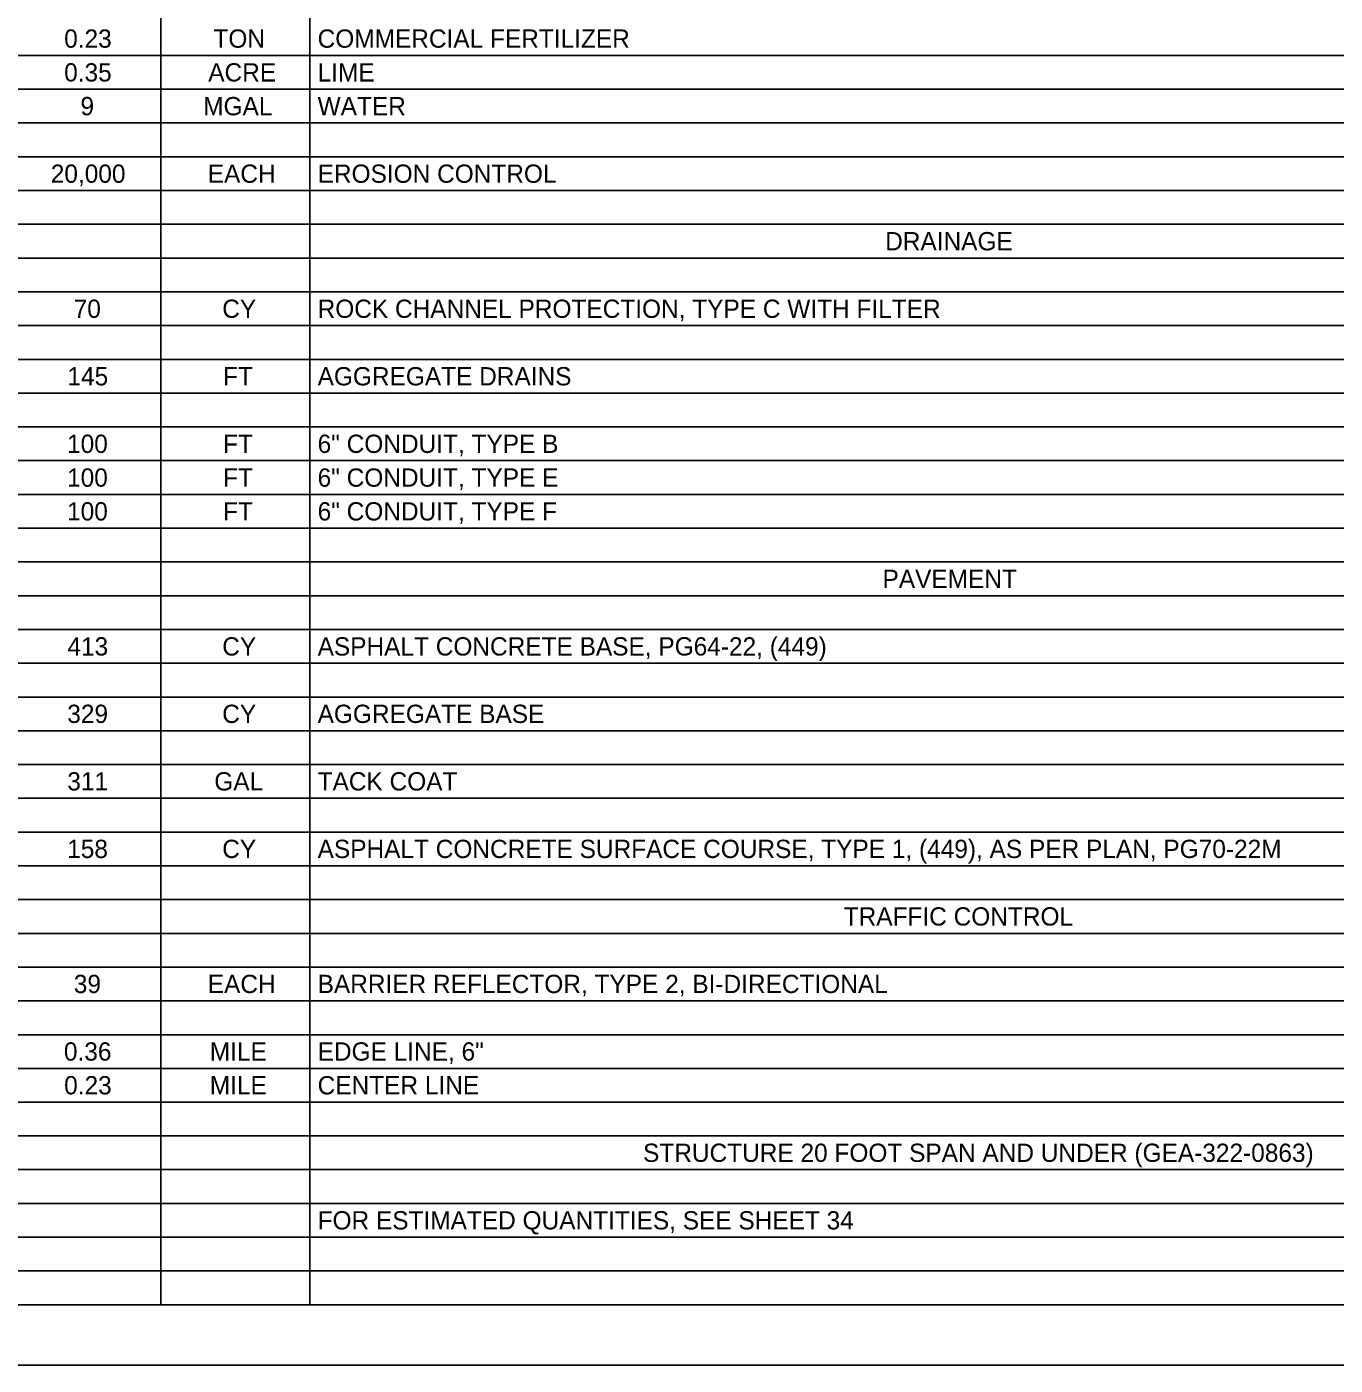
# Model space of a CAD drawing. Extents: x -31.7 to 37.3, y 0 to 22.
# Drawn here: x 18.16 to 29.01, y 0 to 11.1 of the extents above; entities that cross this region are included whole.
import ezdxf

# ---------------------------------------------------------------- set-up
doc = ezdxf.new("R2010")
doc.units = 0
for name, color, linetype in [('SH_Border', 7, 'Continuous'), ('SH_Cut_Line', 7, 'Continuous'), ('SH_Data', 7, 'Continuous'), ('SH_Text', 7, 'Continuous')]:
    doc.layers.add(name, color=color, linetype=linetype)

msp = doc.modelspace()

# ---------------------------------------------------------------- linework, layer by layer
at = {"layer": 'SH_Border'}
msp.add_lwpolyline([(1.5, 21.5), (33.5, 21.5), (33.5, 0.5), (1.5, 0.5)], close=True, dxfattribs=at)
at = {"layer": 'SH_Cut_Line'}
msp.add_lwpolyline([(0, 0), (34, 0), (34, 22), (0, 22)], close=True, dxfattribs=at)
at = {"layer": 'SH_Data'}
for p, q in [((19.27, 21.5), (19.27, 0.502)), ((20.506, 21.5), (20.506, 0.502)), ((1.5, 10.861), (32.001, 10.861)), ((1.5, 10.581), (32.001, 10.581)), ((1.5, 10.301), (32.001, 10.301)), ((1.5, 10.021), (32.001, 10.021)), ((1.5, 9.741), (32.001, 9.741)), ((1.5, 9.461), (32.001, 9.461)), ((1.5, 9.181), (32.001, 9.181)), ((1.5, 8.901), (32.001, 8.901)), ((1.5, 8.621), (32.001, 8.621)), ((1.5, 8.341), (32.001, 8.341)), ((1.5, 8.061), (32.001, 8.061)), ((1.5, 7.781), (32.001, 7.781)), ((1.5, 7.501), (32.001, 7.501)), ((1.5, 7.221), (32.001, 7.221)), ((1.5, 6.941), (32.001, 6.941)), ((1.5, 6.661), (32.001, 6.661)), ((1.5, 6.381), (32.001, 6.381)), ((1.5, 6.101), (32.001, 6.101)), ((1.5, 5.821), (32.001, 5.821)), ((1.5, 5.541), (32.001, 5.541)), ((1.5, 5.261), (32.001, 5.261)), ((1.5, 4.981), (32.001, 4.981)), ((1.5, 4.701), (32.001, 4.701)), ((1.5, 4.421), (32.001, 4.421)), ((1.5, 4.141), (32.001, 4.141)), ((1.5, 3.861), (32.001, 3.861)), ((1.5, 3.581), (32.001, 3.581)), ((1.5, 3.301), (32.001, 3.301)), ((1.5, 3.021), (32.001, 3.021)), ((1.5, 2.741), (32.001, 2.741)), ((1.5, 2.461), (32.001, 2.461)), ((1.5, 2.182), (32.001, 2.182)), ((1.5, 1.902), (32.001, 1.902)), ((1.5, 1.622), (32.001, 1.622)), ((1.5, 1.342), (32.001, 1.342)), ((1.5, 1.062), (32.001, 1.062)), ((1.5, 0.782), (32.001, 0.782)), ((1.5, 0.502), (32.001, 0.502))]:
    msp.add_line(p, q, dxfattribs=at)

# ---------------------------------------------------------------- texts
at = {"layer": 'SH_Text'}
for s, height, p in [('0.23', 0.1515, (18.469, 10.925)), ('TON', 0.1515, (19.707, 10.925)), ('COMMERCIAL FERTILIZER', 0.15152, (20.571, 10.925)), ('0.35', 0.1515, (18.469, 10.645)), ('ACRE', 0.1515, (19.664, 10.645)), ('LIME', 0.1515, (20.571, 10.645)), ('9', 0.152, (18.604, 10.365)), ('MGAL', 0.1515, (19.622, 10.365)), ('WATER', 0.1515, (20.571, 10.365)), ('20,000', 0.1515, (18.358, 9.805)), ('EACH', 0.1515, (19.66, 9.805)), ('EROSION CONTROL', 0.15152, (20.571, 9.805)), ('DRAINAGE', 0.1515, (25.278, 9.245)), ('70', 0.1515, (18.548, 8.685)), ('CY', 0.1515, (19.78, 8.685)), ('ROCK CHANNEL PROTECTION, TYPE C WITH FILTER', 0.15152, (20.571, 8.685)), ('145', 0.1515, (18.496, 8.125)), ('FT', 0.1515, (19.787, 8.125)), ('AGGREGATE DRAINS', 0.15152, (20.571, 8.125)), ('100', 0.1515, (18.493, 7.565)), ('FT', 0.1515, (19.787, 7.565)), ('6" CONDUIT, TYPE B', 0.15152, (20.571, 7.565)), ('100', 0.1515, (18.493, 7.285)), ('FT', 0.1515, (19.787, 7.285)), ('6" CONDUIT, TYPE E', 0.15152, (20.571, 7.285)), ('100', 0.1515, (18.493, 7.005)), ('FT', 0.1515, (19.787, 7.005)), ('6" CONDUIT, TYPE F', 0.15152, (20.571, 7.005)), ('PAVEMENT', 0.1515, (25.256, 6.445)), ('413', 0.1515, (18.496, 5.885)), ('CY', 0.1515, (19.78, 5.885)), ('ASPHALT CONCRETE BASE, PG64-22, (449)', 0.15152, (20.571, 5.885)), ('329', 0.1515, (18.495, 5.326)), ('CY', 0.1515, (19.78, 5.326)), ('AGGREGATE BASE', 0.15152, (20.571, 5.326)), ('311', 0.1515, (18.495, 4.766)), ('GAL', 0.1515, (19.714, 4.766)), ('TACK COAT', 0.1515, (20.571, 4.766)), ('158', 0.1515, (18.494, 4.206)), ('CY', 0.1515, (19.78, 4.206)), ('ASPHALT CONCRETE SURFACE COURSE, TYPE 1, (449), AS PER PLAN, PG70-22M', 0.15152, (20.571, 4.206)), ('TRAFFIC CONTROL', 0.15152, (24.934, 3.646)), ('39', 0.1515, (18.549, 3.086)), ('EACH', 0.1515, (19.66, 3.086)), ('BARRIER REFLECTOR, TYPE 2, BI-DIRECTIONAL', 0.15152, (20.571, 3.086)), ('0.36', 0.1515, (18.467, 2.526)), ('MILE', 0.1515, (19.677, 2.526)), ('EDGE LINE, 6"', 0.15152, (20.571, 2.526)), ('0.23', 0.1515, (18.469, 2.246)), ('MILE', 0.1515, (19.677, 2.246)), ('CENTER LINE', 0.15152, (20.571, 2.246)), ('STRUCTURE 20 FOOT SPAN AND UNDER (GEA-322-0863)', 0.15152, (23.27, 1.686)), ('FOR ESTIMATED QUANTITIES, SEE SHEET 34', 0.15152, (20.571, 1.126))]:
    msp.add_text(s, height=height, dxfattribs=at).set_placement(p)

doc.saveas('drawing.dxf')
